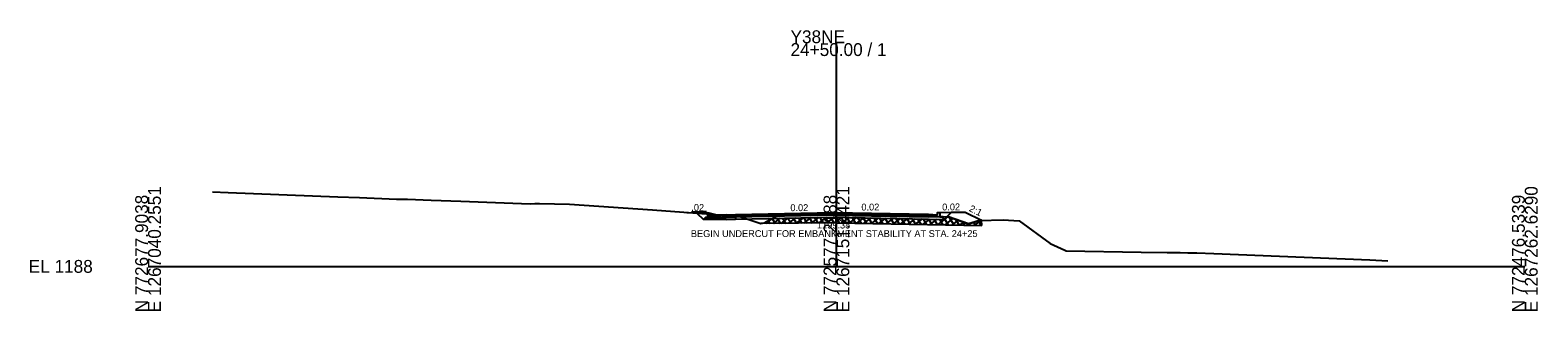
# Model space of a CAD drawing. Extents: x -26 to 1267158, y -10 to 772570.
# Drawn here: x 1274.3 to 1602.8, y -9.7 to 51.5 of the extents above; entities that cross this region are included whole.
import ezdxf

# ---------------------------------------------------------------- set-up
doc = ezdxf.new("R2010")
doc.units = 0
for name, color, linetype in [('Exist Cross Section Cell', 7, 'Continuous'), ('Exist XS Center Line Elevation Label', 7, 'Continuous'), ('Exist XS Ground Line', 7, 'Continuous'), ('Prop CMT Pvmt Course 1', 7, 'Continuous'), ('Prop CMT Pvmt Course 2', 7, 'Continuous'), ('Prop CMT Pvmt Course 3', 7, 'Continuous'), ('Prop CMT Pvmt Course 4', 7, 'Continuous'), ('Prop CMT Shld Paved Course 1', 7, 'Continuous'), ('Prop CMT Shld Paved Course 2', 7, 'Continuous'), ('Prop CMT Slope Grass', 7, 'Continuous'), ('Prop CMT Subgrade Earthwork', 7, 'Continuous'), ('Prop Conc Curb and Gutter', 7, 'Continuous'), ('Prop Corridor Mesh Top', 7, 'Continuous'), ('Prop XS Earthwork Shape', 7, 'Continuous'), ('Prop XS Finish Grade', 7, 'Continuous'), ('Prop XS Label Text', 7, 'Continuous'), ('Prop XS Undercut Exc', 7, 'Continuous'), ('Typical Curb CELL', 7, 'Continuous')]:
    doc.layers.add(name, color=color, linetype=linetype)

msp = doc.modelspace()

# ---------------------------------------------------------------- linework, layer by layer
at = {"layer": 'Exist Cross Section Cell'}
for p, q in [((1450, 0), (1450, 48.65)), ((1300, 0), (1450, 0)), ((1450, 0), (1600, 0))]:
    msp.add_line(p, q, dxfattribs=at)
at = {"layer": 'Exist XS Ground Line'}
msp.add_lwpolyline([(1314.03, 16.22), (1317.46, 16.09), (1341.32, 15.19), (1346.04, 15.02), (1354.16, 14.67), (1355.31, 14.66), (1356.55, 14.63), (1361.71, 14.45), (1368.18, 14.21), (1383.28, 13.64), (1384.26, 13.7), (1385.31, 13.73), (1391.83, 13.53), (1409.89, 12.35), (1426.55, 11.08), (1428.72, 10.98), (1433.51, 9.32), (1434.22, 9.46), (1436.69, 10.87), (1437.76, 11.09), (1438.17, 11.12), (1440.37, 11.3), (1441.76, 11.31), (1450, 11.38), (1450.97, 11.38), (1458.8, 11.28), (1460.69, 11.26), (1463.88, 11.21), (1470.34, 11.14), (1470.67, 11.12), (1472.08, 10.98), (1474.45, 10.78), (1478.77, 9.31), (1481.17, 10.03), (1486.34, 10.15), (1489.8, 9.95), (1496.6, 4.98), (1499.76, 3.52), (1500.04, 3.4), (1516.39, 3.12), (1522.04, 3.03), (1524.91, 2.99), (1526.6, 2.97), (1528.5, 2.96), (1532.22, 2.83), (1566.21, 1.42), (1570.17, 1.19)], dxfattribs=at)
at = {"layer": 'Prop CMT Pvmt Course 1'}
msp.add_lwpolyline([(1428, 11.34), (1449.39, 11.77), (1470.01, 11.36), (1470.01, 11.36), (1470.01, 11.11)], dxfattribs=at)
at = {"layer": 'Prop CMT Pvmt Course 2'}
msp.add_line((1428, 11.33), (1428, 10.3), dxfattribs=at)
msp.add_lwpolyline([(1428, 11.09), (1449.39, 11.52), (1470.01, 11.11), (1470.01, 11.11), (1470.01, 10.86)], dxfattribs=at)
at = {"layer": 'Prop CMT Pvmt Course 3'}
for p, q in [((1421.5, 10.68), (1421.03, 10.22)), ((1422, 10.68), (1421.5, 10.68)), ((1426, 10.68), (1428, 10.76))]:
    msp.add_line(p, q, dxfattribs=at)
for points in [[(1449.38, 11.19), (1428.01, 10.76)], [(1449.38, 11.19), (1470.01, 10.77)]]:
    msp.add_lwpolyline(points, dxfattribs=at)
at = {"layer": 'Prop CMT Pvmt Course 4'}
for points in [[(1473.01, 10.71), (1472.51, 10.72)], [(1473.48, 10.25), (1473.01, 10.71)]]:
    msp.add_lwpolyline(points, dxfattribs=at)
at = {"layer": 'Prop CMT Shld Paved Course 1'}
msp.add_line((1426, 11.26), (1428, 11.34), dxfattribs=at)
at = {"layer": 'Prop CMT Shld Paved Course 2'}
msp.add_line((1426, 11.01), (1428, 11.09), dxfattribs=at)
at = {"layer": 'Prop CMT Slope Grass'}
for p, q in [((1417.42, 11.77), (1422, 11.68)), ((1472.51, 11.74), (1475.08, 11.79))]:
    msp.add_line(p, q, dxfattribs=at)
at = {"layer": 'Prop CMT Subgrade Earthwork'}
for p, q in [((1419.59, 11.61), (1421.03, 10.22)), ((1426, 10.22), (1421.03, 10.22)), ((1426, 10.22), (1428.02, 10.3)), ((1428.02, 10.3), (1449.38, 10.73)), ((1449.38, 10.73), (1473.48, 10.25)), ((1475.08, 11.79), (1473.48, 10.25))]:
    msp.add_line(p, q, dxfattribs=at)
at = {"layer": 'Prop Conc Curb and Gutter'}
msp.add_lwpolyline([(1472.01, 11.24), (1472.01, 11.74), (1472.51, 11.74), (1472.51, 10.72), (1470.01, 10.77), (1470.01, 11.36), (1472.01, 11.24)], dxfattribs=at)
at = {"layer": 'Prop XS Earthwork Shape'}
msp.add_lwpolyline([(1478.02, 11.85), (1481.62, 10.04), (1481.17, 10.03), (1478.77, 9.31), (1474.45, 10.78), (1474.07, 10.81), (1475.08, 11.79)], close=True, dxfattribs=at)
at = {"layer": 'Prop XS Finish Grade'}
msp.add_line((1478.02, 11.85), (1481.62, 10.04), dxfattribs=at)
msp.add_lwpolyline([(1475.08, 11.79), (1478.02, 11.85)], dxfattribs=at)
at = {"layer": 'Prop XS Label Text'}
for p, q in [((1418.44, 11.89), (1421.66, 11.87)), ((1421.66, 11.87), (1421.28, 11.94))]:
    msp.add_line(p, q, dxfattribs=at)
at = {"layer": 'Prop XS Undercut Exc'}
for p, q in [((1434.6, 9.33), (1436.07, 10.46)), ((1435.09, 9.95), (1435.46, 9.34)), ((1435.96, 10.45), (1436.63, 9.36)), ((1436.27, 9.35), (1437.75, 10.5)), ((1437.11, 10.48), (1437.79, 9.37)), ((1437.93, 9.37), (1439.44, 10.53)), ((1438.27, 10.51), (1438.96, 9.38)), ((1439.43, 10.53), (1440.12, 9.39)), ((1439.6, 9.39), (1441.13, 10.56)), ((1440.59, 10.55), (1441.29, 9.41)), ((1441.27, 9.41), (1442.82, 10.6)), ((1441.74, 10.58), (1442.45, 9.42)), ((1442.9, 10.6), (1443.62, 9.43)), ((1442.93, 9.43), (1444.5, 10.63)), ((1444.06, 10.62), (1444.78, 9.45)), ((1444.6, 9.44), (1446.19, 10.66)), ((1445.22, 10.64), (1445.95, 9.46)), ((1446.26, 9.46), (1447.88, 10.7)), ((1446.38, 10.67), (1447.11, 9.47)), ((1447.54, 10.69), (1448.28, 9.48)), ((1447.93, 9.48), (1449.55, 10.72)), ((1448.7, 10.71), (1449.45, 9.5)), ((1449.6, 9.5), (1451.15, 10.69)), ((1449.87, 10.72), (1450.62, 9.49)), ((1451.06, 10.69), (1451.81, 9.47)), ((1451.22, 9.48), (1452.76, 10.66)), ((1452.24, 10.67), (1453, 9.45)), ((1452.82, 9.45), (1454.36, 10.63)), ((1453.43, 10.65), (1454.18, 9.42)), ((1454.42, 9.42), (1455.96, 10.6)), ((1454.62, 10.62), (1455.37, 9.4)), ((1455.81, 10.6), (1456.56, 9.38)), ((1456.03, 9.39), (1457.56, 10.56)), ((1457, 10.58), (1457.74, 9.36)), ((1457.63, 9.36), (1459.16, 10.53)), ((1458.18, 10.55), (1458.93, 9.33)), ((1459.23, 9.33), (1460.76, 10.5)), ((1459.37, 10.53), (1460.12, 9.31)), ((1460.56, 10.5), (1461.31, 9.29)), ((1460.84, 9.3), (1462.36, 10.47)), ((1461.75, 10.48), (1462.49, 9.27)), ((1462.44, 9.27), (1463.96, 10.44)), ((1462.93, 10.46), (1463.68, 9.24)), ((1464.04, 9.24), (1465.56, 10.4)), ((1464.12, 10.43), (1464.87, 9.22)), ((1465.31, 10.41), (1466.05, 9.2)), ((1465.65, 9.21), (1467.17, 10.37)), ((1466.5, 10.39), (1467.24, 9.18)), ((1467.25, 9.18), (1468.77, 10.34)), ((1467.69, 10.36), (1468.43, 9.15)), ((1468.85, 9.15), (1470.37, 10.31)), ((1468.87, 10.34), (1469.61, 9.13)), ((1470.06, 10.31), (1470.8, 9.11)), ((1470.46, 9.11), (1471.97, 10.28)), ((1471.25, 10.29), (1471.99, 9.09)), ((1472.06, 9.08), (1474.28, 10.79)), ((1472.44, 10.27), (1473.18, 9.06)), ((1473.57, 10.33), (1474.36, 9.04)), ((1473.66, 9.05), (1475.46, 10.43)), ((1474.47, 10.78), (1475.55, 9.02)), ((1475.26, 9.02), (1476.6, 10.05)), ((1475.96, 10.27), (1476.74, 9)), ((1480.07, 8.93), (1481.52, 10.04)), ((1480.85, 9.94), (1481.48, 8.91)), ((1481.67, 8.9), (1481.62, 10.04)), ((1450, 9.5), (1433.51, 9.32)), ((1434.22, 9.46), (1434.3, 9.33)), ((1450, 9.5), (1481.67, 8.9)), ((1476.87, 8.99), (1477.74, 9.66)), ((1477.44, 9.77), (1477.92, 8.97)), ((1478.47, 8.96), (1479.03, 9.39)), ((1478.87, 9.34), (1479.11, 8.95)), ((1479.86, 9.64), (1480.3, 8.93))]:
    msp.add_line(p, q, dxfattribs=at)
at = {"layer": 'Typical Curb CELL'}
for p, q in [((1422, 10.68), (1422, 11.68)), ((1424, 11.18), (1422, 11.68)), ((1422, 10.68), (1426, 10.68)), ((1422.03, 11.14), (1422.19, 11.18)), ((1422.17, 11.09), (1422.03, 11.14)), ((1422.19, 11.18), (1422.17, 11.09)), ((1422.7, 11.05), (1422.6, 10.98)), ((1422.6, 10.98), (1422.77, 10.94)), ((1422.77, 10.94), (1422.7, 11.05)), ((1423.44, 11.11), (1423.41, 11)), ((1423.41, 11), (1423.53, 10.99)), ((1423.53, 10.99), (1423.44, 11.11)), ((1423.95, 11.05), (1423.85, 10.98)), ((1423.85, 10.98), (1424.01, 10.94)), ((1424.01, 10.94), (1423.95, 11.05)), ((1426, 11.26), (1424, 11.18)), ((1424.69, 11.11), (1424.66, 11)), ((1424.66, 11), (1424.78, 10.99)), ((1424.78, 10.99), (1424.69, 11.11)), ((1425.41, 10.91), (1425.3, 10.83)), ((1425.3, 10.83), (1425.47, 10.8)), ((1425.47, 10.8), (1425.41, 10.91)), ((1425.74, 11.15), (1425.71, 11.04)), ((1425.71, 11.04), (1425.83, 11.03)), ((1425.83, 11.03), (1425.74, 11.15)), ((1426, 10.68), (1426, 11.26))]:
    msp.add_line(p, q, dxfattribs=at)
for centre in [(1422.06, 11.22), (1422.16, 10.95), (1422.17, 11.39), (1422.25, 10.84), (1422.28, 11), (1422.37, 11.37), (1422.54, 11.03), (1422.55, 10.98), (1422.73, 10.89), (1422.75, 11.29), (1422.76, 10.99), (1422.95, 10.95), (1422.95, 10.77), (1423, 11.07), (1423.11, 11.23), (1423.12, 11.04), (1423.16, 10.91), (1423.21, 10.95), (1423.26, 10.82), (1423.41, 10.95), (1423.53, 11), (1423.56, 11.14), (1423.62, 10.99), (1423.63, 10.79), (1423.72, 10.94), (1423.77, 11.09), (1423.78, 11.03), (1423.8, 10.98), (1423.97, 10.88), (1424.01, 10.99), (1424.09, 10.8), (1424.2, 10.95), (1424.25, 11.07), (1424.3, 11.04), (1424.32, 10.76), (1424.37, 11.04), (1424.41, 10.91), (1424.46, 10.95), (1424.52, 11.13), (1424.64, 10.77), (1424.89, 11.2), (1424.93, 11.08), (1425.13, 10.85), (1425.28, 11.12), (1425.49, 11.13), (1425.57, 10.9), (1425.74, 10.76), (1425.86, 10.93), (1425.9, 11.16)]:
    msp.add_circle(centre, 0.00802, dxfattribs=at)

# ---------------------------------------------------------------- texts
at = {"layer": 'Exist Cross Section Cell'}
for s, p in [('Y38NE', (1440, 48.65)), ('24+50.00 / 1', (1440, 45.85)), ('EL 1188', (1274, -1.4))]:
    msp.add_text(s, height=2.8, dxfattribs=at).set_placement(p)
for s, p in [('E 1267040.2551', (1302.8, -10)), ('E 1267151.4421', (1452.8, -10)), ('E 1267262.6290', (1602.8, -10)), ('N 772677.9038', (1300, -10)), ('N 772577.2188', (1450, -10)), ('N 772476.5339', (1600, -10))]:
    msp.add_text(s, height=2.8, rotation=90, dxfattribs=at).set_placement(p)
at = {"layer": 'Exist XS Center Line Elevation Label'}
for s, p in [('BEGIN UNDERCUT FOR EMBANKMENT STABILITY AT STA. 24+25', (1418.28, 6.39)), ('1199.38', (1445.76, 8.26))]:
    msp.add_text(s, height=1.5, dxfattribs=at).set_placement(p)
at = {"layer": 'Prop Corridor Mesh Top'}
for p in [(1428, 11.33), (1450, 11.77), (1470.01, 11.36), (1472.01, 11.24), (1485.74, 10.99)]:
    msp.add_text('X', height=0.00025, dxfattribs=at).set_placement(p)
at = {"layer": 'Prop XS Label Text'}
for s, rotation, p in [('.02', 358.9817, (1418.36, 12.11)), ('0.02', 0.3087, (1439.96, 12.03)), ('0.02', 0.3087, (1455.44, 12.17)), ('0.02', 0.3087, (1473.04, 12.19)), ('2:1', 333.5442, (1478.77, 12.12))]:
    msp.add_text(s, height=1.5, rotation=rotation, dxfattribs=at).set_placement(p)

doc.saveas('drawing.dxf')
